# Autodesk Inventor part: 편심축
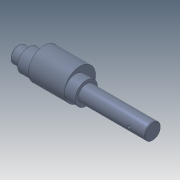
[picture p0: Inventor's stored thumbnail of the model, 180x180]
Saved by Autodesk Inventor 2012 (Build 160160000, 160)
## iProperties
Manager: 한국ATC센터
Company: 한국ATC센터
Created: 2014-07
Part Number: 편심축
Document SubType Name: Modeling
Designer: KYOUNG IL JANG
Density: 7.86 g/cm^3
Material: 강, 연강
Mass: 1544.74 g
Surface Area: 256.354 cm^2
Volume: 196.531 cm^3
Author: KYOUNG IL JANG
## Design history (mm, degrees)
sketch "스케치1"
  geometry: L1 (-105, 0)-(105, 0); L2 (-105, 0)-(-105, 12.5); L3 (-105, 12.5)-(-89, 12.5); L4 (-89, 12.5)-(-89, 17.5); L5 (-89, 17.5)-(-82, 17.5); L6 (-82, 17.5)-(-82, 12.5); L7 (-82, 12.5)-(-0.35, 12.5); L8 (-0.35, 12.5)-(-0.35, 11.95); L9 (-0.35, 11.95)-(1, 11.95); L10 (1, 11.95)-(1, 12.5); L11 (1, 12.5)-(105, 12.5); L12 (105, 12.5)-(105, 0); L13 (70, 12.5)-(70, 9.1); L14 (70, 9.1)-(95, 9.1); L15 (95, 9.1)-(95, 12.5); L16 (80, -12.5)-(82.5, -12.5); L17 (82.5, -12.5)-(80, -10); L18 (80, -10)-(80, -12.5); L19 (1, 12.5)-(-0.35, 12.5); 2 further points
  constraints: 38 end point, 8 parallel, 5 collinear, 5 perpendicular, 2 point on line, 1 coincident, 1 horizontal, 1 midpoint, 1 vertical
  dimensions: "d0" = 210 distance of L1.start L1.end; "d1" = 25 diameter of L3 L1; "d2" = 35 diameter of L5 L1; "d3" = 16 distance of L2.end L3.end; "d6" = 1.35 distance of L8.end L9.end; "d7" = 23.9 diameter of L9 L1; "d8" = 3.4 distance between parallel lines of L14 L11; "d9" = 10 distance between parallel lines of L15 L12; "d10" = 25 distance of L13.end L14.end; "d11" = 25 diameter of L16 L1 (= d1); "d12" = 25 distance from line of L12 L16.start; "d13" = 45 deg angle of L17 L18; "d14" = 5 diameter of L16.end L18; "d27" = 104 distance between parallel lines of L10 L12; "d35" = 7 distance of L4.end L5.end
revolve "회전1" stored, may be unused: angle "d15" = 90 deg
revolve "회전2" stored, may be unused: angle "d16" = 90 deg
extrude "돌출1" cut sketch "스케치1" stored distance "d17" = 8; taper "d18" = 0 deg
fillet "모깎기1" dims "d19" = 4
node "작업 평면1"
sketch "스케치2"
  geometry: C1 r 12.5 at (0, 0) reference; C2 r 17.5 at (0, 0); C3 r 24.5 at (0, 7); 1 further point
  constraints: 2 centre point, 1 coincident, 1 tangent, 1 vertical alignment
  dimensions: "d32" = 35 diameter of C2; "d33" = 49 diameter of C3 (derived); "d34" = 7 distance of C3.centre point (0, 0)
extrude "돌출2" join sketch "스케치2" distance "d22" = 56; taper "d23" = 0 deg
chamfer "모따기1" distance "d24" = 1; stored, may be unused: second distance "d25" = 2, angle "d26" = 45 deg
feature "면 이동1" dims "d31" = 83
node "솔리드1"
